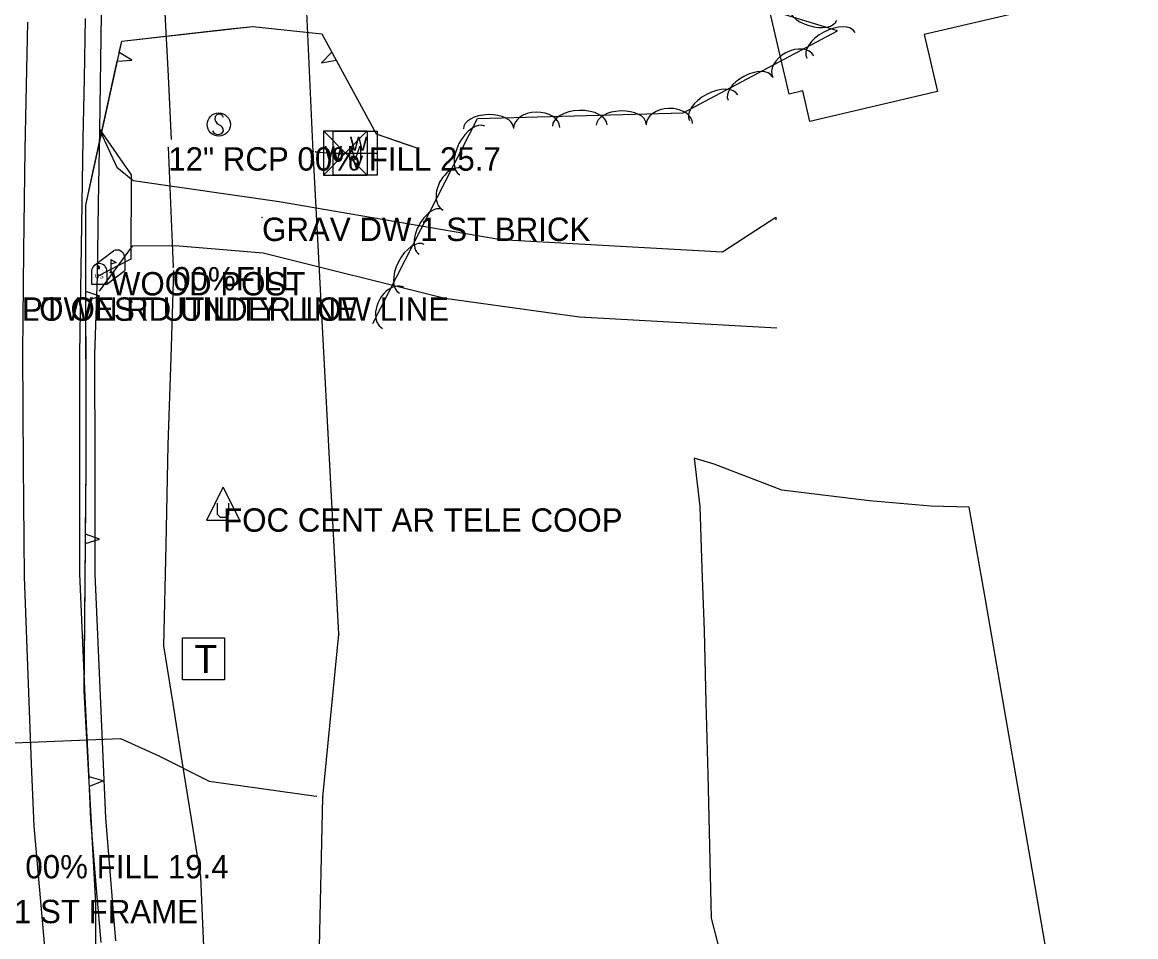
# Model space of a CAD drawing. Extents: x 954793 to 988390, y 1867850 to 1924428.
# Drawn here: x 960953.6 to 961191.8, y 1903553.9 to 1903749.7 of the extents above; entities that cross this region are included whole.
import ezdxf

# ---------------------------------------------------------------- set-up
doc = ezdxf.new("R2010")
doc.units = 0
for name, color, linetype in [('S_BUILDING', 7, 'Continuous'), ('S_DITCHLINE', 7, 'Continuous'), ('S_DRG_PT_SYM', 7, 'Continuous'), ('S_DRIVEWAY', 7, 'Continuous'), ('S_EDGE_BITUMINOUS', 7, 'Continuous'), ('S_EDGE_PAVEMENT', 7, 'Continuous'), ('S_ELECTRIC_UTILITIES_ANNOT', 7, 'Continuous'), ('S_MAILBOX', 7, 'Continuous'), ('S_MAILBOX_ANNOT', 7, 'Continuous'), ('S_MSC_PT_SYM', 7, 'Continuous'), ('S_OBSCURES', 7, 'Continuous'), ('S_PAVEMENT_CROWN', 7, 'Continuous'), ('S_SHOULDER', 7, 'Continuous'), ('S_SIDE_DRAIN', 7, 'Continuous'), ('S_SIDE_DRAIN_ANNOT', 7, 'Continuous'), ('S_SIGN', 7, 'Continuous'), ('S_SURVEY_TEXT_ANNOT', 7, 'Continuous'), ('S_TELEPHONE_UTILITIES', 7, 'Continuous'), ('S_TREE', 7, 'Continuous'), ('S_UNDERGROUND_CABLE', 7, 'Continuous'), ('S_UTILITY_POLE_ANNOT', 7, 'Continuous'), ('S_UTL_PT_SYM', 7, 'Continuous'), ('S_WATER_UTILITIES', 7, 'Continuous')]:
    doc.layers.add(name, color=color, linetype=linetype)

msp = doc.modelspace()

# ---------------------------------------------------------------- linework, layer by layer
at = {"layer": 'S_BUILDING'}
msp.add_lwpolyline([(961117.66, 1903734.32), (961109.22, 1903770.47), (961110.95, 1903770.87), (961107.05, 1903787.56), (961143.17, 1903796), (961147.15, 1903778.99), (961165.57, 1903783.29), (961172.62, 1903753.14), (961146.57, 1903747.05), (961149.42, 1903734.86), (961122.08, 1903728.47), (961120.56, 1903734.99)], close=True, dxfattribs=at)
at = {"layer": 'S_DITCHLINE'}
for points in [[(960985.53, 1903724.62), (960984.87, 1903738.14), (960984.21, 1903751.66), (960981.97, 1903775.88), (960979.73, 1903800.1)], [(961026.6, 1903375.34), (961020.59, 1903377.01), (961014.25, 1903397.47), (961009.18, 1903402.61), (961006.22, 1903417.01), (961003.26, 1903431.41), (961000.3, 1903445.8), (960997.35, 1903460.2), (960996.47, 1903475.22), (960995.6, 1903490.24), (960994.72, 1903505.26), (960993.85, 1903520.28), (960992.82, 1903543.53), (960991.79, 1903566.79), (960989.82, 1903579.15), (960987.85, 1903591.5), (960985.88, 1903603.86), (960983.92, 1903616.21), (960984.37, 1903637.73), (960984.82, 1903659.24), (960985.44, 1903677.91), (960986.07, 1903696.58)]]:
    msp.add_lwpolyline(points, dxfattribs=at)
at = {"layer": 'S_DRG_PT_SYM'}
for points in [[(960984.85, 1903722.93), (960984.85, 1903722.98), (960984.85, 1903722.93), (960984.8, 1903722.93), (960984.85, 1903722.93), (960984.85, 1903722.88), (960984.85, 1903722.93), (960984.9, 1903722.93)], [(960985.9, 1903697.29), (960985.9, 1903697.34), (960985.9, 1903697.29), (960985.85, 1903697.29), (960985.9, 1903697.29), (960985.9, 1903697.24), (960985.9, 1903697.29), (960985.95, 1903697.29)]]:
    msp.add_lwpolyline(points, dxfattribs=at)
at = {"layer": 'S_DRIVEWAY'}
for points in [[(960970.26, 1903726.37), (960973.87, 1903718.7), (960977.34, 1903715.84), (961008.55, 1903711.31), (961055.96, 1903703.21), (961103.39, 1903700.52), (961114.84, 1903707.94)], [(961114.84, 1903707.94), (961114.83, 1903707.37)], [(961115.02, 1903684.21), (961072.83, 1903686.56), (961044, 1903690.58), (961005.17, 1903700.25), (960986.35, 1903701.87), (960977.12, 1903701.75), (960970.06, 1903692.11)]]:
    msp.add_lwpolyline(points, dxfattribs=at)
at = {"layer": 'S_EDGE_BITUMINOUS'}
msp.add_lwpolyline([(960970.16, 1903726.82), (960976.94, 1903717.05), (960976.83, 1903699.01), (960969.63, 1903695.28)], dxfattribs=at)
at = {"layer": 'S_EDGE_PAVEMENT'}
msp.add_lwpolyline([(960967.1, 1903750.53), (960966.84, 1903737.63), (960966.57, 1903724.73), (960966.2, 1903701.7), (960965.83, 1903678.66), (960965.83, 1903655.12), (960965.83, 1903631.59), (960966.43, 1903618.47), (960967.02, 1903605.35), (960967.62, 1903592.23), (960968.21, 1903579.12), (960969.31, 1903565.92), (960970.41, 1903552.73)], dxfattribs=at)
at = {"layer": 'S_MAILBOX'}
for p, q in [((960968.97, 1903697.64), (960973.1, 1903700.75)), ((960972.58, 1903698.93), (960972.58, 1903696.22)), ((960975.53, 1903699.28), (960975.53, 1903696.56)), ((960968.41, 1903696.37), (960968.41, 1903693.66)), ((960971.74, 1903693.66), (960975.53, 1903696.56)), ((960971.74, 1903696.37), (960971.74, 1903693.66)), ((960968.41, 1903693.66), (960971.74, 1903693.66))]:
    msp.add_line(p, q, dxfattribs=at)
for points in [[(960969.6, 1903697.49), (960969.82, 1903697.35), (960969.82, 1903696.96), (960970.12, 1903696.96), (960970.12, 1903697.32), (960969.93, 1903697.57), (960969.6, 1903697.51)], [(960972.58, 1903698.93), (960973.69, 1903698.27), (960972.58, 1903697.92)]]:
    msp.add_lwpolyline(points, dxfattribs=at)
for centre, end in [((960973.87, 1903699.28), 117.5718), ((960970.08, 1903696.37), 180)]:
    msp.add_arc(centre, 1.66, 0, end, dxfattribs=at)
msp.add_ellipse((960972.58, 1903696.22), major_axis=(0.145, 0.132), ratio=0.564646, dxfattribs=at)
at = {"layer": 'S_MSC_PT_SYM'}
msp.add_lwpolyline([(961004.92, 1903707.87), (961004.92, 1903707.92), (961004.92, 1903707.87), (961004.87, 1903707.87), (961004.92, 1903707.87), (961004.92, 1903707.82), (961004.92, 1903707.87), (961004.97, 1903707.87)], dxfattribs=at)
at = {"layer": 'S_OBSCURES'}
msp.add_lwpolyline([(961173.38, 1903546.94), (961169.94, 1903566.73), (961166.51, 1903586.53), (961163.07, 1903606.32), (961159.63, 1903626.11), (961156.19, 1903645.91), (961147.98, 1903646.11), (961134.88, 1903647.24), (961116.08, 1903649.54), (961101.59, 1903655.13), (961097.32, 1903656.36), (961098.53, 1903646.07), (961099, 1903632.75), (961099.47, 1903619.43), (961099.85, 1903604.05), (961100.24, 1903588.68), (961100.62, 1903573.31), (961101, 1903557.94), (961105.87, 1903538.79)], dxfattribs=at)
at = {"layer": 'S_PAVEMENT_CROWN'}
msp.add_lwpolyline([(960954.76, 1903749.73), (960954.47, 1903736.13), (960954.18, 1903722.53), (960953.91, 1903700.74), (960953.65, 1903678.96), (960953.83, 1903654.98), (960954.01, 1903630.99), (960954.53, 1903617.65), (960955.04, 1903604.31), (960955.55, 1903590.96), (960956.06, 1903577.62), (960957.23, 1903564.7), (960958.4, 1903551.78)], dxfattribs=at)
msp.add_lwpolyline([(960954.76, 1903749.73), (960954.47, 1903736.13), (960954.18, 1903722.53), (960953.91, 1903700.74), (960953.65, 1903678.96), (960953.83, 1903654.98), (960954.01, 1903630.99), (960954.53, 1903617.65), (960955.04, 1903604.31), (960955.55, 1903590.96), (960956.06, 1903577.62), (960957.23, 1903564.7), (960958.4, 1903551.78)], dxfattribs=at)
at = {"layer": 'S_SHOULDER'}
msp.add_lwpolyline([(960970.5, 1903751.45), (960970.16, 1903726.61), (960969.89, 1903710.93), (960969.63, 1903695.26), (960969.1, 1903678.6), (960969.11, 1903655.09), (960969.13, 1903631.58), (960969.7, 1903618.54), (960970.28, 1903605.49), (960970.86, 1903592.45), (960971.43, 1903579.4), (960972.5, 1903566.22), (960973.58, 1903553.04)], dxfattribs=at)
at = {"layer": 'S_SIDE_DRAIN'}
msp.add_line((960984.85, 1903722.93), (960985.9, 1903697.29), dxfattribs=at)
at = {"layer": 'S_SIGN'}
msp.add_circle((960995.65, 1903727.79), 2.49, dxfattribs=at)
for centre, radius, start, end in [((960996.33, 1903729.11), 1.5, 167.1196, 241.9813), ((960995.72, 1903729.05), 0.95, 16.5258, 156.8957), ((960995.49, 1903726.96), 1.28, 204.641, 335.359), ((960995.23, 1903726.44), 1.4, 358.6529, 73.7063)]:
    msp.add_arc(centre, radius, start, end, dxfattribs=at)
at = {"layer": 'S_TELEPHONE_UTILITIES'}
msp.add_lwpolyline([(960987.89, 1903608.92), (960987.89, 1903617.92), (960996.89, 1903617.92), (960996.89, 1903608.92)], close=True, dxfattribs=at)
at = {"layer": 'S_TREE'}
for p, q in [((960977.08, 1903741.61), (960974.37, 1903743.25)), ((961019.84, 1903743.28), (961017.65, 1903741.02)), ((960973.95, 1903741.33), (960977.08, 1903741.61)), ((961017.65, 1903741.02), (961020.78, 1903741.55)), ((960970.24, 1903691.04), (960967.24, 1903692.06)), ((960967.24, 1903690.09), (960970.24, 1903691.04)), ((960970.17, 1903639.04), (960967.18, 1903640.09)), ((960967.17, 1903638.13), (960970.17, 1903639.04)), ((960970.95, 1903587.29), (960967.9, 1903588.15)), ((960968, 1903586.19), (960970.95, 1903587.29))]:
    msp.add_line(p, q, dxfattribs=at)
for points in [[(961028.59, 1903685.24), (961051.03, 1903729.1), (961094.97, 1903730.31), (961127.99, 1903747.89), (961092.32, 1903758.86)], [(961191.79, 1903289.17), (961167.46, 1903305.44), (961127.27, 1903305.78), (961086.78, 1903299.67), (961055.23, 1903296.87), (961021.48, 1903299.02), (961020.54, 1903333.07), (961020.8, 1903363.26), (961006.92, 1903386.27), (961001.53, 1903412.72), (960985.05, 1903449.92), (960969.2, 1903506.46), (960969.36, 1903561.06), (960966.89, 1903606.68), (960967.31, 1903654.48), (960967.2, 1903710.57), (960974.9, 1903745.64), (961002.91, 1903748.81), (961017.71, 1903747.22), (961029.3, 1903725.78), (961038, 1903722.82)], [(960974.37, 1903743.25), (960974.9, 1903745.64), (960997.31, 1903748.18)], [(960997.31, 1903748.18), (961002.91, 1903748.81), (961017.71, 1903747.22), (961019.84, 1903743.28)], [(960968.59, 1903716.91), (960973.95, 1903741.33)], [(961020.78, 1903741.55), (961029.3, 1903725.78), (961035.68, 1903723.61)], [(961035.68, 1903723.61), (961038, 1903722.82)], [(960967.24, 1903692.06), (960967.2, 1903710.57), (960968.59, 1903716.91)], [(960967.29, 1903665.09), (960967.24, 1903690.09)], [(960967.18, 1903640.09), (960967.31, 1903654.48), (960967.29, 1903665.09)], [(960966.95, 1903613.12), (960967.17, 1903638.13)], [(960967.9, 1903588.15), (960966.89, 1903606.68), (960966.95, 1903613.12)], [(960969.35, 1903561.22), (960968, 1903586.19)], [(960969.29, 1903536.22), (960969.36, 1903561.06), (960969.35, 1903561.22)]]:
    msp.add_lwpolyline(points, dxfattribs=at)
for centre, major_axis, ratio, start_param, end_param in [((961122.72, 1903751.73), (5.11, -1.57), 0.540576, 3.141593, 6.283185), ((961126.6, 1903744.75), (-5.18, -2.76), 0.550079, 3.141593, 6.283185), ((961118.55, 1903740.17), (-4.37, -2.33), 0.68531, 3.141593, 6.283185), ((961109.33, 1903735.55), (-4.72, -2.51), 0.540699, 3.141593, 6.283185), ((961101.51, 1903731.39), (-5.18, -2.76), 0.550079, 3.141593, 6.283185), ((961063.64, 1903727.06), (-4.95, -0.14), 0.685245, 3.141593, 6.283185), ((961072.89, 1903727.58), (-5.87, -0.16), 0.550027, 3.141593, 6.283185), ((961081.75, 1903727.82), (-5.34, -0.15), 0.540647, 3.141593, 6.283185), ((961092.05, 1903727.85), (-4.95, -0.14), 0.685245, 3.141593, 6.283185), ((961049.9, 1903722.24), (-2.67, -5.22), 0.55001, 3.141605, 6.283197), ((961053.33, 1903727.04), (-5.34, -0.15), 0.540647, 3.141593, 6.283185), ((961045.91, 1903713.88), (-2.26, -4.41), 0.685223, 3.141612, 6.283205), ((961040.99, 1903704.83), (-2.44, -4.76), 0.54063, 3.141604, 6.283197), ((961036.95, 1903696.93), (-2.67, -5.22), 0.55001, 3.141605, 6.283197), ((961032.96, 1903688.57), (-2.26, -4.41), 0.685223, 3.141612, 6.283205)]:
    msp.add_ellipse(centre, major_axis=major_axis, ratio=ratio, start_param=start_param, end_param=end_param, dxfattribs=at)
at = {"layer": 'S_UNDERGROUND_CABLE'}
for p, q in [((960996.58, 1903650.17), (960993.06, 1903643.08)), ((960996.58, 1903650.17), (961000.07, 1903643.08)), ((960995.38, 1903644.32), (960995.38, 1903646.76)), ((960997.75, 1903646.76), (960997.75, 1903644.32)), ((960993.06, 1903643.08), (961000.07, 1903643.08)), ((960996, 1903643.66), (960995.38, 1903644.32)), ((960997.2, 1903643.66), (960996, 1903643.66)), ((960997.75, 1903644.32), (960997.2, 1903643.66))]:
    msp.add_line(p, q, dxfattribs=at)
at = {"layer": 'S_UTL_PT_SYM'}
for points in [[(961015.86, 1903722.03), (961015.86, 1903722.08), (961015.86, 1903722.03), (961015.81, 1903722.03), (961015.86, 1903722.03), (961015.86, 1903721.98), (961015.86, 1903722.03), (961015.91, 1903722.03)], [(961016.39, 1903721.96), (961016.39, 1903722.01), (961016.39, 1903721.96), (961016.34, 1903721.96), (961016.39, 1903721.96), (961016.39, 1903721.91), (961016.39, 1903721.96), (961016.44, 1903721.96)], [(961021.97, 1903721.5), (961021.97, 1903721.55), (961021.97, 1903721.5), (961021.92, 1903721.5), (961021.97, 1903721.5), (961021.97, 1903721.45), (961021.97, 1903721.5), (961022.02, 1903721.5)], [(961021.34, 1903618.71), (961021.34, 1903618.76), (961021.34, 1903618.71), (961021.29, 1903618.71), (961021.34, 1903618.71), (961021.34, 1903618.66), (961021.34, 1903618.71), (961021.39, 1903618.71)], [(960974.66, 1903596.36), (960974.66, 1903596.41), (960974.66, 1903596.36), (960974.61, 1903596.36), (960974.66, 1903596.36), (960974.66, 1903596.31), (960974.66, 1903596.36), (960974.71, 1903596.36)], [(960982.85, 1903592.67), (960982.85, 1903592.72), (960982.85, 1903592.67), (960982.8, 1903592.67), (960982.85, 1903592.67), (960982.85, 1903592.62), (960982.85, 1903592.67), (960982.9, 1903592.67)], [(960993.62, 1903587.21), (960993.62, 1903587.26), (960993.62, 1903587.21), (960993.57, 1903587.21), (960993.62, 1903587.21), (960993.62, 1903587.16), (960993.62, 1903587.21), (960993.67, 1903587.21)], [(961016.51, 1903584.04), (961016.51, 1903584.09), (961016.51, 1903584.04), (961016.46, 1903584.04), (961016.51, 1903584.04), (961016.51, 1903583.99), (961016.51, 1903584.04), (961016.56, 1903584.04)], [(961017.91, 1903583.83), (961017.91, 1903583.88), (961017.91, 1903583.83), (961017.86, 1903583.83), (961017.91, 1903583.83), (961017.91, 1903583.78), (961017.91, 1903583.83), (961017.96, 1903583.83)]]:
    msp.add_lwpolyline(points, dxfattribs=at)
at = {"layer": 'S_WATER_UTILITIES'}
for p, q in [((961015.86, 1903722.03), (961012.52, 1903795.09)), ((961018.06, 1903726.45), (961027.39, 1903726.45)), ((961018.06, 1903726.45), (961018.06, 1903716.96)), ((961018.06, 1903726.45), (961027.39, 1903716.96)), ((961027.39, 1903726.45), (961018.06, 1903716.96)), ((961020.12, 1903726.35), (961029.54, 1903726.35)), ((961020.12, 1903716.94), (961020.12, 1903726.35)), ((961027.39, 1903726.45), (961027.39, 1903716.96)), ((961029.54, 1903726.35), (961029.54, 1903716.94)), ((961021.34, 1903618.71), (961015.86, 1903722.03)), ((961016.39, 1903721.96), (961021.97, 1903721.5)), ((961020.12, 1903721.66), (961029.54, 1903721.66)), ((961018.06, 1903716.96), (961027.39, 1903716.96)), ((961029.54, 1903716.94), (961020.12, 1903716.94)), ((961017.91, 1903583.83), (961021.34, 1903618.71)), ((960940.14, 1903595.01), (960974.66, 1903596.36)), ((960974.66, 1903596.36), (960982.85, 1903592.67)), ((960982.85, 1903592.67), (960993.62, 1903587.21)), ((960993.62, 1903587.21), (961016.51, 1903584.04)), ((961016.63, 1903523.67), (961017.91, 1903583.83))]:
    msp.add_line(p, q, dxfattribs=at)

# ---------------------------------------------------------------- texts
at = {"layer": 'S_ELECTRIC_UTILITIES_ANNOT'}
msp.add_text('LOWEST UTILITY LINE', height=5, dxfattribs=at).set_placement((960953.54, 1903685.79))
at = {"layer": 'S_MAILBOX'}
msp.add_text('US', height=0.96, rotation=360, dxfattribs=at).set_placement((960969.18, 1903694.85))
at = {"layer": 'S_MAILBOX_ANNOT'}
msp.add_text('WOOD POST', height=5, dxfattribs=at).set_placement((960972.58, 1903691.22))
at = {"layer": 'S_SIDE_DRAIN_ANNOT'}
for s, p in [('12" RCP 00% FILL 25.7', (960984.85, 1903717.93)), ('00%FILL', (960985.9, 1903692.29)), ('18" RCP 00% FILL 19.4', (960926.64, 1903566.43))]:
    msp.add_text(s, height=5, dxfattribs=at).set_placement(p)
at = {"layer": 'S_SURVEY_TEXT_ANNOT'}
for s, p in [('GRAV DW 1 ST BRICK', (961004.92, 1903702.87)), ('PT ON RD UNDER LOW LINE', (960953.54, 1903685.79)), ('GRAV DW 1 ST FRAME', (960918.04, 1903556.84))]:
    msp.add_text(s, height=5, dxfattribs=at).set_placement(p)
at = {"layer": 'S_TELEPHONE_UTILITIES'}
msp.add_text('T', height=6, rotation=360, dxfattribs=at).set_placement((960990.45, 1903610.42))
at = {"layer": 'S_UTILITY_POLE_ANNOT'}
msp.add_text('FOC CENT AR TELE COOP', height=5, dxfattribs=at).set_placement((960996.58, 1903640.64))
at = {"layer": 'S_WATER_UTILITIES'}
for s, p in [('W', (961023.67, 1903722.2)), ('W M', (961018.26, 1903720.22)), ('V', (961023.91, 1903718.13))]:
    msp.add_text(s, height=3, rotation=360, dxfattribs=at).set_placement(p)

doc.saveas('drawing.dxf')
